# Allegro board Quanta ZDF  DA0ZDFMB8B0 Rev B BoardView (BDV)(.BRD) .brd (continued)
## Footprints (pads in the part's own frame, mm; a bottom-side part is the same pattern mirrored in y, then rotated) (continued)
BGA32-DIALOG-DA7219-02VBA
  round 0.254 smd: A1(-0.51,-2.025) A3(-0.51,-1.485) A5(-0.51,-0.945) A7(-0.51,-0.405) A9(-0.51,0.135) A11(-0.51,0.675) A13(-0.51,1.215) A15(-0.51,1.755) B2(-0.17,-1.755) B4(-0.17,-1.215) B6(-0.17,-0.675) B8(-0.17,-0.135) B10(-0.17,0.405) B12(-0.17,0.945) B14(-0.17,1.485) B16(-0.17,2.025) C1(0.17,-2.025) C3(0.17,-1.485) C5(0.17,-0.945) C7(0.17,-0.405) C9(0.17,0.135) C11(0.17,0.675) C13(0.17,1.215) C15(0.17,1.755) D2(0.51,-1.755) D4(0.51,-1.215) D6(0.51,-0.675) D8(0.51,-0.135) D10(0.51,0.405) D12(0.51,0.945) D14(0.51,1.485) D16(0.51,2.025)
BGA56-TEXAS-SN74AVC16T245
  round 0.356 smd: A1(-2.925,-1.625) A2(-2.925,-0.975) A3(-2.925,-0.325) A4(-2.925,0.325) A5(-2.925,0.975) A6(-2.925,1.625) B1(-2.275,-1.625) B2(-2.275,-0.975) B3(-2.275,-0.325) B4(-2.275,0.325) B5(-2.275,0.975) B6(-2.275,1.625) C1(-1.625,-1.625) C2(-1.625,-0.975) C3(-1.625,-0.325) C4(-1.625,0.325) C5(-1.625,0.975) C6(-1.625,1.625) D1(-0.975,-1.625) D2(-0.975,-0.975) D3(-0.975,-0.325) D4(-0.975,0.325) D5(-0.975,0.975) D6(-0.975,1.625) E1(-0.325,-1.625) E2(-0.325,-0.975) E5(-0.325,0.975) E6(-0.325,1.625) F1(0.325,-1.625) F2(0.325,-0.975) F5(0.325,0.975) F6(0.325,1.625) G1(0.975,-1.625) G2(0.975,-0.975) G3(0.975,-0.325) G4(0.975,0.325) G5(0.975,0.975) G6(0.975,1.625) H1(1.625,-1.625) H2(1.625,-0.975) H3(1.625,-0.325) H4(1.625,0.325) H5(1.625,0.975) H6(1.625,1.625) J1(2.275,-1.625) J2(2.275,-0.975) J3(2.275,-0.325) J4(2.275,0.325) J5(2.275,0.975) J6(2.275,1.625) K1(2.925,-1.625) K2(2.925,-0.975) K3(2.925,-0.325) K4(2.925,0.325) K5(2.925,0.975) K6(2.925,1.625)
BGA64-ANALOGIX-ANX7625
  round 0.254 smd: A1(-1.4,-1.4) A2(-1.4,-1) A3(-1.4,-0.6) A4(-1.4,-0.2) A5(-1.4,0.2) A6(-1.4,0.6) A7(-1.4,1) A8(-1.4,1.4) B1(-1,-1.4) B2(-1,-1) B3(-1,-0.6) B4(-1,-0.2) B5(-1,0.2) B6(-1,0.6) B7(-1,1) B8(-1,1.4) C1(-0.6,-1.4) C2(-0.6,-1) C3(-0.6,-0.6) C4(-0.6,-0.2) C5(-0.6,0.2) C6(-0.6,0.6) C7(-0.6,1) C8(-0.6,1.4) D1(-0.2,-1.4) D2(-0.2,-1) D3(-0.2,-0.6) D4(-0.2,-0.2) D5(-0.2,0.2) D6(-0.2,0.6) D7(-0.2,1) D8(-0.2,1.4) E1(0.2,-1.4) E2(0.2,-1) E3(0.2,-0.6) E4(0.2,-0.2) E5(0.2,0.2) E6(0.2,0.6) E7(0.2,1) E8(0.2,1.4) F1(0.6,-1.4) F2(0.6,-1) F3(0.6,-0.6) F4(0.6,-0.2) F5(0.6,0.2) F6(0.6,0.6) F7(0.6,1) F8(0.6,1.4) G1(1,-1.4) G2(1,-1) G3(1,-0.6) G4(1,-0.2) G5(1,0.2) G6(1,0.6) G7(1,1) G8(1,1.4) H1(1.4,-1.4) H2(1.4,-1) H3(1.4,-0.6) H4(1.4,-0.2) H5(1.4,0.2) H6(1.4,0.6) H7(1.4,1) H8(1.4,1.4)
BGA64-ST-SMT32F098RC-0_5S
  round 0.254 smd: A1(-1.75,-1.75) A2(-1.75,-1.25) A3(-1.75,-0.75) A4(-1.75,-0.25) A5(-1.75,0.25) A6(-1.75,0.75) A7(-1.75,1.25) A8(-1.75,1.75) B1(-1.25,-1.75) B2(-1.25,-1.25) B3(-1.25,-0.75) B4(-1.25,-0.25) B5(-1.25,0.25) B6(-1.25,0.75) B7(-1.25,1.25) B8(-1.25,1.75) C1(-0.75,-1.75) C2(-0.75,-1.25) C3(-0.75,-0.75) C4(-0.75,-0.25) C5(-0.75,0.25) C6(-0.75,0.75) C7(-0.75,1.25) C8(-0.75,1.75) D1(-0.25,-1.75) D2(-0.25,-1.25) D3(-0.25,-0.75) D4(-0.25,-0.25) D5(-0.25,0.25) D6(-0.25,0.75) D7(-0.25,1.25) D8(-0.25,1.75) E1(0.25,-1.75) E2(0.25,-1.25) E3(0.25,-0.75) E4(0.25,-0.25) E5(0.25,0.25) E6(0.25,0.75) E7(0.25,1.25) E8(0.25,1.75) F1(0.75,-1.75) F2(0.75,-1.25) F3(0.75,-0.75) F4(0.75,-0.25) F5(0.75,0.25) F6(0.75,0.75) F7(0.75,1.25) F8(0.75,1.75) G1(1.25,-1.75) G2(1.25,-1.25) G3(1.25,-0.75) G4(1.25,-0.25) G5(1.25,0.25) G6(1.25,0.75) G7(1.25,1.25) G8(1.25,1.75) H1(1.75,-1.75) H2(1.75,-1.25) H3(1.75,-0.75) H4(1.75,-0.25) H5(1.75,0.25) H6(1.75,0.75) H7(1.75,1.25) H8(1.75,1.75)
BGA78-GOOGLE-UR0605B
  round 0.254 smd: A1(-2,-2) A2(-2,-1.5) A3(-2,-1) A4(-2,-0.5) A5(-2,0) A6(-2,0.5) A7(-2,1) A8(-2,1.5) A9(-2,2) B1(-1.5,-2) B2(-1.5,-1.5) B3(-1.5,-1) B4(-1.5,-0.5) B5(-1.5,0) B6(-1.5,0.5) B7(-1.5,1) B8(-1.5,1.5) B9(-1.5,2) C1(-1,-2) C2(-1,-1.5) C3(-1,-1) C4(-1,-0.5) C5(-1,0) C7(-1,1) C8(-1,1.5) C9(-1,2) D1(-0.5,-2) D2(-0.5,-1.5) D4(-0.5,-0.5) D5(-0.5,0) D6(-0.5,0.5) D7(-0.5,1) D8(-0.5,1.5) D9(-0.5,2) E1(0,-2) E2(0,-1.5) E3(0,-1) E4(0,-0.5) E5(0,0) E6(0,0.5) E7(0,1) E8(0,1.5) E9(0,2) F1(0.5,-2) F2(0.5,-1.5) F3(0.5,-1) F4(0.5,-0.5) F5(0.5,0) F6(0.5,0.5) F7(0.5,1) F8(0.5,1.5) F9(0.5,2) G1(1,-2) G2(1,-1.5) G3(1,-1) G5(1,0) G6(1,0.5) G7(1,1) G8(1,1.5) G9(1,2) H1(1.5,-2) H2(1.5,-1.5) H3(1.5,-1) H4(1.5,-0.5) H5(1.5,0) H6(1.5,0.5) H7(1.5,1) H8(1.5,1.5) H9(1.5,2) J1(2,-2) J2(2,-1.5) J3(2,-1) J4(2,-0.5) J5(2,0) J6(2,0.5) J7(2,1) J8(2,1.5) J9(2,2)
BGA153-SANDISK-SDIN7DP4-16G
  round 0.254 smd: A1(-3.25,-3.25) A2(-3.25,-2.75) A3(-3.25,-2.25) A4(-3.25,-1.75) A5(-3.25,-1.25) A6(-3.25,-0.75) A7(-3.25,-0.25) A8(-3.25,0.25) A9(-3.25,0.75) A10(-3.25,1.25) A11(-3.25,1.75) A12(-3.25,2.25) A13(-3.25,2.75) A14(-3.25,3.25) B1(-2.75,-3.25) B2(-2.75,-2.75) B3(-2.75,-2.25) B4(-2.75,-1.75) B5(-2.75,-1.25) B6(-2.75,-0.75) B7(-2.75,-0.25) B8(-2.75,0.25) B9(-2.75,0.75) B10(-2.75,1.25) B11(-2.75,1.75) B12(-2.75,2.25) B13(-2.75,2.75) B14(-2.75,3.25) C1(-2.25,-3.25) C2(-2.25,-2.75) C3(-2.25,-2.25) C4(-2.25,-1.75) C5(-2.25,-1.25) C6(-2.25,-0.75) C7(-2.25,-0.25) C8(-2.25,0.25) C9(-2.25,0.75) C10(-2.25,1.25) C11(-2.25,1.75) C12(-2.25,2.25) C13(-2.25,2.75) C14(-2.25,3.25) D1(-1.75,-3.25) D2(-1.75,-2.75) D3(-1.75,-2.25) D4(-1.75,-1.75) D12(-1.75,2.25) D13(-1.75,2.75) D14(-1.75,3.25) E1(-1.25,-3.25) E2(-1.25,-2.75) E3(-1.25,-2.25) E5(-1.25,-1.25) E6(-1.25,-0.75) E7(-1.25,-0.25) E8(-1.25,0.25) E9(-1.25,0.75) E10(-1.25,1.25) E12(-1.25,2.25) E13(-1.25,2.75) E14(-1.25,3.25) F1(-0.75,-3.25) F2(-0.75,-2.75) F3(-0.75,-2.25) F5(-0.75,-1.25) F10(-0.75,1.25) F12(-0.75,2.25) F13(-0.75,2.75) F14(-0.75,3.25) G1(-0.25,-3.25) G2(-0.25,-2.75) G3(-0.25,-2.25) G5(-0.25,-1.25) G10(-0.25,1.25) G12(-0.25,2.25) G13(-0.25,2.75) G14(-0.25,3.25) H1(0.25,-3.25) H2(0.25,-2.75) H3(0.25,-2.25) H5(0.25,-1.25) H10(0.25,1.25) H12(0.25,2.25) H13(0.25,2.75) H14(0.25,3.25) J1(0.75,-3.25) J2(0.75,-2.75) J3(0.75,-2.25) J5(0.75,-1.25) J10(0.75,1.25) J12(0.75,2.25) J13(0.75,2.75) J14(0.75,3.25) K1(1.25,-3.25) K2(1.25,-2.75) K3(1.25,-2.25) K5(1.25,-1.25) K6(1.25,-0.75) K7(1.25,-0.25) K8(1.25,0.25) K9(1.25,0.75) K10(1.25,1.25) K12(1.25,2.25) K13(1.25,2.75) K14(1.25,3.25) L1(1.75,-3.25) L2(1.75,-2.75) L3(1.75,-2.25) L12(1.75,2.25) L13(1.75,2.75) L14(1.75,3.25) M1(2.25,-3.25) M2(2.25,-2.75) M3(2.25,-2.25) M4(2.25,-1.75) M5(2.25,-1.25) M6(2.25,-0.75) M7(2.25,-0.25) M8(2.25,0.25) M9(2.25,0.75) M10(2.25,1.25) M11(2.25,1.75) M12(2.25,2.25) M13(2.25,2.75) M14(2.25,3.25) N1(2.75,-3.25) N2(2.75,-2.75) N3(2.75,-2.25) N4(2.75,-1.75) N5(2.75,-1.25) N6(2.75,-0.75) N7(2.75,-0.25) N8(2.75,0.25) N9(2.75,0.75) N10(2.75,1.25) N11(2.75,1.75) N12(2.75,2.25) N13(2.75,2.75) N14(2.75,3.25) P1(3.25,-3.25) P2(3.25,-2.75) P3(3.25,-2.25) P4(3.25,-1.75) P5(3.25,-1.25) P6(3.25,-0.75) P7(3.25,-0.25) P8(3.25,0.25) P9(3.25,0.75) P10(3.25,1.25) P11(3.25,1.75) P12(3.25,2.25) P13(3.25,2.75) P14(3.25,3.25)
BGA194-MEDIATEK-MT6358-0_5S
  round 0.254 smd: A1(-2.8,-3) A2(-2.8,-2.6) A3(-2.8,-2.2) A4(-2.8,-1.8) A5(-2.8,-1.4) A6(-2.8,-1) A7(-2.8,-0.6) A8(-2.8,-0.2) A9(-2.8,0.2) A10(-2.8,0.6) A11(-2.8,1) A12(-2.8,1.4) A13(-2.8,1.8) A14(-2.8,2.2) A15(-2.8,2.6) A16(-2.8,3) B1(-2.4,-3) B2(-2.4,-2.6) B3(-2.4,-2.2) B4(-2.4,-1.8) B6(-2.4,-1) B7(-2.4,-0.6) B8(-2.4,-0.2) B9(-2.4,0.2) B10(-2.4,0.6) B11(-2.4,1) B12(-2.4,1.4) B13(-2.4,1.8) B14(-2.4,2.2) B15(-2.4,2.6) B16(-2.4,3) C1(-2,-3) C15(-2,2.6) C16(-2,3) D2(-1.6,-2.6) D3(-1.6,-2.2) D4(-1.6,-1.8) D5(-1.6,-1.4) D6(-1.6,-1) D7(-1.6,-0.6) D8(-1.6,-0.2) D9(-1.6,0.2) D10(-1.6,0.6) D11(-1.6,1) D12(-1.6,1.4) D13(-1.6,1.8) D14(-1.6,2.2) D15(-1.6,2.6) D16(-1.6,3) E1(-1.2,-3) E2(-1.2,-2.6) E3(-1.2,-2.2) E4(-1.2,-1.8) E5(-1.2,-1.4) E6(-1.2,-1) E7(-1.2,-0.6) E8(-1.2,-0.2) E9(-1.2,0.2) E12(-1.2,1.4) E14(-1.2,2.2) F1(-0.8,-3) F2(-0.8,-2.6) F3(-0.8,-2.2) F5(-0.8,-1.4) F6(-0.8,-1) F7(-0.8,-0.6) F8(-0.8,-0.2) F9(-0.8,0.2) F10(-0.8,0.6) F11(-0.8,1) F12(-0.8,1.4) F13(-0.8,1.8) F14(-0.8,2.2) F15(-0.8,2.6) F16(-0.8,3) G2(-0.4,-2.6) G4(-0.4,-1.8) G5(-0.4,-1.4) G6(-0.4,-1) G7(-0.4,-0.6) G8(-0.4,-0.2) G9(-0.4,0.2) G10(-0.4,0.6) G11(-0.4,1) G12(-0.4,1.4) G13(-0.4,1.8) G15(-0.4,2.6) G16(-0.4,3) H1(0,-3) H2(0,-2.6) H4(0,-1.8) H5(0,-1.4) H6(0,-1) H7(0,-0.6) H8(0,-0.2) H9(0,0.2) H10(0,0.6) H11(0,1) H13(0,1.8) H15(0,2.6) J3(0.4,-2.2) J4(0.4,-1.8) J5(0.4,-1.4) J6(0.4,-1) J7(0.4,-0.6) J8(0.4,-0.2) J9(0.4,0.2) J10(0.4,0.6) J11(0.4,1) J13(0.4,1.8) J15(0.4,2.6) J16(0.4,3) K1(0.8,-3) K3(0.8,-2.2) K4(0.8,-1.8) K5(0.8,-1.4) K6(0.8,-1) K10(0.8,0.6) K12(0.8,1.4) K13(0.8,1.8) K15(0.8,2.6) K16(0.8,3) L1(1.2,-3) L3(1.2,-2.2) L4(1.2,-1.8) L5(1.2,-1.4) L6(1.2,-1) L7(1.2,-0.6) L8(1.2,-0.2) L9(1.2,0.2) L10(1.2,0.6) L11(1.2,1) L12(1.2,1.4) L13(1.2,1.8) L14(1.2,2.2) L15(1.2,2.6) L16(1.2,3) M2(1.6,-2.6) M3(1.6,-2.2) M4(1.6,-1.8) M5(1.6,-1.4) M6(1.6,-1) M7(1.6,-0.6) M8(1.6,-0.2) M9(1.6,0.2) M10(1.6,0.6) M11(1.6,1) M12(1.6,1.4) M13(1.6,1.8) M14(1.6,2.2) M15(1.6,2.6) N1(2,-3) N2(2,-2.6) N4(2,-1.8) N6(2,-1) N7(2,-0.6) N8(2,-0.2) N9(2,0.2) N10(2,0.6) N11(2,1) N12(2,1.4) N13(2,1.8) N14(2,2.2) N15(2,2.6) N16(2,3) P1(2.4,-3) P2(2.4,-2.6) P3(2.4,-2.2) P4(2.4,-1.8) P5(2.4,-1.4) P6(2.4,-1) P7(2.4,-0.6) P8(2.4,-0.2) P9(2.4,0.2) P10(2.4,0.6) P11(2.4,1) P12(2.4,1.4) P13(2.4,1.8) P14(2.4,2.2) P15(2.4,2.6) P16(2.4,3) R1(2.8,-3) R2(2.8,-2.6) R3(2.8,-2.2) R5(2.8,-1.4) R6(2.8,-1) R7(2.8,-0.6) R9(2.8,0.2) R10(2.8,0.6) R11(2.8,1) R13(2.8,1.8) R14(2.8,2.2) R15(2.8,2.6) R16(2.8,3)
BGA200-HYNIX-H9HCNNN8RUMLHR
  round 0.254 smd: A1(-6.825,-4.4) A2(-6.825,-3.6) A3(-6.825,-2.8) A4(-6.825,-2) A5(-6.825,-1.2) A8(-6.825,1.2) A9(-6.825,2) A10(-6.825,2.8) A11(-6.825,3.6) A12(-6.825,4.4) AA1(6.175,-4.4) AA2(6.175,-3.6) AA3(6.175,-2.8) AA4(6.175,-2) AA5(6.175,-1.2) AA8(6.175,1.2) AA9(6.175,2) AA10(6.175,2.8) AA11(6.175,3.6) AA12(6.175,4.4) AB1(6.825,-4.4) AB2(6.825,-3.6) AB3(6.825,-2.8) AB4(6.825,-2) AB5(6.825,-1.2) AB8(6.825,1.2) AB9(6.825,2) AB10(6.825,2.8) AB11(6.825,3.6) AB12(6.825,4.4) B1(-6.175,-4.4) B2(-6.175,-3.6) B3(-6.175,-2.8) B4(-6.175,-2) B5(-6.175,-1.2) B8(-6.175,1.2) B9(-6.175,2) B10(-6.175,2.8) B11(-6.175,3.6) B12(-6.175,4.4) C1(-5.525,-4.4) C2(-5.525,-3.6) C3(-5.525,-2.8) C4(-5.525,-2) C5(-5.525,-1.2) C8(-5.525,1.2) C9(-5.525,2) C10(-5.525,2.8) C11(-5.525,3.6) C12(-5.525,4.4) D1(-4.875,-4.4) D2(-4.875,-3.6) D3(-4.875,-2.8) D4(-4.875,-2) D5(-4.875,-1.2) D8(-4.875,1.2) D9(-4.875,2) D10(-4.875,2.8) D11(-4.875,3.6) D12(-4.875,4.4) E1(-4.225,-4.4) E2(-4.225,-3.6) E3(-4.225,-2.8) E4(-4.225,-2) E5(-4.225,-1.2) E8(-4.225,1.2) E9(-4.225,2) E10(-4.225,2.8) E11(-4.225,3.6) E12(-4.225,4.4) F1(-3.575,-4.4) F2(-3.575,-3.6) F3(-3.575,-2.8) F4(-3.575,-2) F5(-3.575,-1.2) F8(-3.575,1.2) F9(-3.575,2) F10(-3.575,2.8) F11(-3.575,3.6) F12(-3.575,4.4) G1(-2.925,-4.4) G2(-2.925,-3.6) G3(-2.925,-2.8) G4(-2.925,-2) G5(-2.925,-1.2) G8(-2.925,1.2) G9(-2.925,2) G10(-2.925,2.8) G11(-2.925,3.6) G12(-2.925,4.4) H1(-2.275,-4.4) H2(-2.275,-3.6) H3(-2.275,-2.8) H4(-2.275,-2) H5(-2.275,-1.2) H8(-2.275,1.2) H9(-2.275,2) H10(-2.275,2.8) H11(-2.275,3.6) H12(-2.275,4.4) J1(-1.625,-4.4) J2(-1.625,-3.6) J3(-1.625,-2.8) J4(-1.625,-2) J5(-1.625,-1.2) J8(-1.625,1.2) J9(-1.625,2) J10(-1.625,2.8) J11(-1.625,3.6) J12(-1.625,4.4) K1(-0.975,-4.4) K2(-0.975,-3.6) K3(-0.975,-2.8) K4(-0.975,-2) K5(-0.975,-1.2) K8(-0.975,1.2) K9(-0.975,2) K10(-0.975,2.8) K11(-0.975,3.6) K12(-0.975,4.4) N1(0.975,-4.4) N2(0.975,-3.6) N3(0.975,-2.8) N4(0.975,-2) N5(0.975,-1.2) N8(0.975,1.2) N9(0.975,2) N10(0.975,2.8) N11(0.975,3.6) N12(0.975,4.4) P1(1.625,-4.4) P2(1.625,-3.6) P3(1.625,-2.8) P4(1.625,-2) P5(1.625,-1.2) P8(1.625,1.2) P9(1.625,2) P10(1.625,2.8) P11(1.625,3.6) P12(1.625,4.4) R1(2.275,-4.4) R2(2.275,-3.6) R3(2.275,-2.8) R4(2.275,-2) R5(2.275,-1.2) R8(2.275,1.2) R9(2.275,2) R10(2.275,2.8) R11(2.275,3.6) R12(2.275,4.4) T1(2.925,-4.4) T2(2.925,-3.6) T3(2.925,-2.8) T4(2.925,-2) T5(2.925,-1.2) T8(2.925,1.2) T9(2.925,2) T10(2.925,2.8) T11(2.925,3.6) T12(2.925,4.4) U1(3.575,-4.4) U2(3.575,-3.6) U3(3.575,-2.8) U4(3.575,-2) U5(3.575,-1.2) U8(3.575,1.2) U9(3.575,2) U10(3.575,2.8) U11(3.575,3.6) U12(3.575,4.4) V1(4.225,-4.4) V2(4.225,-3.6) V3(4.225,-2.8) V4(4.225,-2) V5(4.225,-1.2) V8(4.225,1.2) V9(4.225,2) V10(4.225,2.8) V11(4.225,3.6) V12(4.225,4.4) W1(4.875,-4.4) W2(4.875,-3.6) W3(4.875,-2.8) W4(4.875,-2) W5(4.875,-1.2) W8(4.875,1.2) W9(4.875,2) W10(4.875,2.8) W11(4.875,3.6) W12(4.875,4.4) Y1(5.525,-4.4) Y2(5.525,-3.6) Y3(5.525,-2.8) Y4(5.525,-2) Y5(5.525,-1.2) Y8(5.525,1.2) Y9(5.525,2) Y10(5.525,2.8) Y11(5.525,3.6) Y12(5.525,4.4)
BGA599-MEDIA-MT8183-0_5S
  round 0.254 smd: A1(-5.6,-5.2) A2(-5.6,-4.8) A3(-5.6,-4.4) A5(-5.6,-3.6) A7(-5.6,-2.8) A9(-5.6,-2) A11(-5.6,-1.2) A13(-5.6,-0.4) A15(-5.6,0.4) A17(-5.6,1.2) A19(-5.6,2) A21(-5.6,2.8) A22(-5.6,3.2) A24(-5.6,4) A26(-5.6,4.8) A27(-5.6,5.2) AA1(2.4,-5.2) AA2(2.4,-4.8) AA3(2.4,-4.4) AA4(2.4,-4) AA5(2.4,-3.6) AA6(2.4,-3.2) AA7(2.4,-2.8) AA10(2.4,-1.6) AA12(2.4,-0.8) AA13(2.4,-0.4) AA15(2.4,0.4) AA17(2.4,1.2) AA19(2.4,2) AA21(2.4,2.8) AA22(2.4,3.2) AA23(2.4,3.6) AA24(2.4,4) AA25(2.4,4.4) AA26(2.4,4.8) AA27(2.4,5.2) AB1(2.8,-5.2) AB2(2.8,-4.8) AB4(2.8,-4) AB5(2.8,-3.6) AB6(2.8,-3.2) AB7(2.8,-2.8) AB8(2.8,-2.4) AB9(2.8,-2) AB13(2.8,-0.4) AB14(2.8,0) AB16(2.8,0.8) AB18(2.8,1.6) AB20(2.8,2.4) AB21(2.8,2.8) AB22(2.8,3.2) AB23(2.8,3.6) AB24(2.8,4) AB25(2.8,4.4) AB26(2.8,4.8) AB27(2.8,5.2) AC2(3.2,-4.8) AC3(3.2,-4.4) AC4(3.2,-4) AC5(3.2,-3.6) AC6(3.2,-3.2) AC7(3.2,-2.8) AC9(3.2,-2) AC10(3.2,-1.6) AC11(3.2,-1.2) AC12(3.2,-0.8) AC13(3.2,-0.4) AC14(3.2,0) AC15(3.2,0.4) AC17(3.2,1.2) AC19(3.2,2) AC22(3.2,3.2) AC23(3.2,3.6) AC24(3.2,4) AC25(3.2,4.4) AC26(3.2,4.8) AD1(3.6,-5.2) AD2(3.6,-4.8) AD4(3.6,-4) AD5(3.6,-3.6) AD6(3.6,-3.2) AD7(3.6,-2.8) AD8(3.6,-2.4) AD9(3.6,-2) AD10(3.6,-1.6) AD16(3.6,0.8) AD19(3.6,2) AD20(3.6,2.4) AD21(3.6,2.8) AD22(3.6,3.2) AD23(3.6,3.6) AD24(3.6,4) AD25(3.6,4.4) AD26(3.6,4.8) AD27(3.6,5.2) AE1(4,-5.2) AE2(4,-4.8) AE3(4,-4.4) AE4(4,-4) AE5(4,-3.6) AE6(4,-3.2) AE7(4,-2.8) AE10(4,-1.6) AE11(4,-1.2) AE12(4,-0.8) AE13(4,-0.4) AE14(4,0) AE15(4,0.4) AE16(4,0.8) AE17(4,1.2) AE18(4,1.6) AE19(4,2) AE20(4,2.4) AE21(4,2.8) AE22(4,3.2) AE23(4,3.6) AE24(4,4) AE25(4,4.4) AE26(4,4.8) AE27(4,5.2) AF2(4.4,-4.8) AF3(4.4,-4.4) AF4(4.4,-4) AF5(4.4,-3.6) AF6(4.4,-3.2) AF7(4.4,-2.8) AF8(4.4,-2.4) AF9(4.4,-2) AF11(4.4,-1.2) AF12(4.4,-0.8) AF13(4.4,-0.4) AF14(4.4,0) AF15(4.4,0.4) AF16(4.4,0.8) AF17(4.4,1.2) AF18(4.4,1.6) AF19(4.4,2) AF20(4.4,2.4) AF21(4.4,2.8) AF22(4.4,3.2) AF23(4.4,3.6) AF24(4.4,4) AF25(4.4,4.4) AF26(4.4,4.8) AG1(4.8,-5.2) AG2(4.8,-4.8) AG3(4.8,-4.4) AG4(4.8,-4) AG5(4.8,-3.6) AG6(4.8,-3.2) AG7(4.8,-2.8) AG8(4.8,-2.4) AG9(4.8,-2) AG11(4.8,-1.2) AG12(4.8,-0.8) AG13(4.8,-0.4) AG14(4.8,0) AG15(4.8,0.4) AG16(4.8,0.8) AG17(4.8,1.2) AG18(4.8,1.6) AG19(4.8,2) AG20(4.8,2.4) AG21(4.8,2.8) AG22(4.8,3.2) AG23(4.8,3.6) AG24(4.8,4) AG25(4.8,4.4) AG26(4.8,4.8) AG27(4.8,5.2) AH1(5.2,-5.2) AH2(5.2,-4.8) AH3(5.2,-4.4) AH4(5.2,-4) AH5(5.2,-3.6) AH6(5.2,-3.2) AH7(5.2,-2.8) AH8(5.2,-2.4) AH9(5.2,-2) AH10(5.2,-1.6) AH11(5.2,-1.2) AH12(5.2,-0.8) AH13(5.2,-0.4) AH14(5.2,0) AH15(5.2,0.4) AH16(5.2,0.8) AH17(5.2,1.2) AH18(5.2,1.6) AH19(5.2,2) AH20(5.2,2.4) AH21(5.2,2.8) AH22(5.2,3.2) AH23(5.2,3.6) AH24(5.2,4) AH25(5.2,4.4) AH26(5.2,4.8) AH27(5.2,5.2) AJ1(5.6,-5.2) AJ2(5.6,-4.8) AJ4(5.6,-4) AJ5(5.6,-3.6) AJ7(5.6,-2.8) AJ8(5.6,-2.4) AJ9(5.6,-2) AJ10(5.6,-1.6) AJ12(5.6,-0.8) AJ13(5.6,-0.4) AJ15(5.6,0.4) AJ16(5.6,0.8) AJ18(5.6,1.6) AJ21(5.6,2.8) AJ22(5.6,3.2) AJ24(5.6,4) AJ25(5.6,4.4) AJ26(5.6,4.8) AJ27(5.6,5.2) B1(-5.2,-5.2) B2(-5.2,-4.8) B3(-5.2,-4.4) B4(-5.2,-4) B5(-5.2,-3.6) B6(-5.2,-3.2) B7(-5.2,-2.8) B9(-5.2,-2) B10(-5.2,-1.6) B11(-5.2,-1.2) B13(-5.2,-0.4) B14(-5.2,0) B15(-5.2,0.4) B17(-5.2,1.2) B18(-5.2,1.6) B19(-5.2,2) B21(-5.2,2.8) B22(-5.2,3.2) B23(-5.2,3.6) B24(-5.2,4) B25(-5.2,4.4) B26(-5.2,4.8) B27(-5.2,5.2) C1(-4.8,-5.2) C2(-4.8,-4.8) C3(-4.8,-4.4) C4(-4.8,-4) C5(-4.8,-3.6) C6(-4.8,-3.2) C7(-4.8,-2.8) C8(-4.8,-2.4) C9(-4.8,-2) C10(-4.8,-1.6) C11(-4.8,-1.2) C12(-4.8,-0.8) C13(-4.8,-0.4) C14(-4.8,0) C15(-4.8,0.4) C16(-4.8,0.8) C17(-4.8,1.2) C18(-4.8,1.6) C19(-4.8,2) C20(-4.8,2.4) C21(-4.8,2.8) C22(-4.8,3.2) C23(-4.8,3.6) C24(-4.8,4) C25(-4.8,4.4) C26(-4.8,4.8) C27(-4.8,5.2) D1(-4.4,-5.2) D2(-4.4,-4.8) D3(-4.4,-4.4) D4(-4.4,-4) D5(-4.4,-3.6) D6(-4.4,-3.2) D7(-4.4,-2.8) D8(-4.4,-2.4) D9(-4.4,-2) D10(-4.4,-1.6) D11(-4.4,-1.2) D12(-4.4,-0.8) D14(-4.4,0) D15(-4.4,0.4) D16(-4.4,0.8) D17(-4.4,1.2) D18(-4.4,1.6) D19(-4.4,2) D20(-4.4,2.4) D21(-4.4,2.8) D22(-4.4,3.2) D23(-4.4,3.6) D24(-4.4,4) D25(-4.4,4.4) D26(-4.4,4.8) E2(-4,-4.8) E3(-4,-4.4) E4(-4,-4) E5(-4,-3.6) E6(-4,-3.2) E7(-4,-2.8) E8(-4,-2.4) E9(-4,-2) E10(-4,-1.6) E11(-4,-1.2) E12(-4,-0.8) E13(-4,-0.4) E14(-4,0) E15(-4,0.4) E16(-4,0.8) E17(-4,1.2) E18(-4,1.6) E19(-4,2) E20(-4,2.4) E21(-4,2.8) E22(-4,3.2) E24(-4,4) E25(-4,4.4) E26(-4,4.8) E27(-4,5.2) F1(-3.6,-5.2) F2(-3.6,-4.8) F3(-3.6,-4.4) F4(-3.6,-4) F5(-3.6,-3.6) F9(-3.6,-2) F10(-3.6,-1.6) F11(-3.6,-1.2) F12(-3.6,-0.8) F13(-3.6,-0.4) F16(-3.6,0.8) F17(-3.6,1.2) F18(-3.6,1.6) F19(-3.6,2) F20(-3.6,2.4) F21(-3.6,2.8) F23(-3.6,3.6) F24(-3.6,4) F25(-3.6,4.4) F26(-3.6,4.8) F27(-3.6,5.2) G1(-3.2,-5.2) G2(-3.2,-4.8) G3(-3.2,-4.4) G4(-3.2,-4) G5(-3.2,-3.6) G6(-3.2,-3.2) G9(-3.2,-2) G14(-3.2,0) G15(-3.2,0.4) G18(-3.2,1.6) G21(-3.2,2.8) G23(-3.2,3.6) G24(-3.2,4) G25(-3.2,4.4) G26(-3.2,4.8) H2(-2.8,-4.8) H3(-2.8,-4.4) H4(-2.8,-4) H5(-2.8,-3.6) H6(-2.8,-3.2) H8(-2.8,-2.4) H10(-2.8,-1.6) H11(-2.8,-1.2) H12(-2.8,-0.8) H13(-2.8,-0.4) H16(-2.8,0.8) H17(-2.8,1.2) H19(-2.8,2) H21(-2.8,2.8) H22(-2.8,3.2) H23(-2.8,3.6) H24(-2.8,4) H25(-2.8,4.4) H26(-2.8,4.8) H27(-2.8,5.2) J1(-2.4,-5.2) J2(-2.4,-4.8) J3(-2.4,-4.4) J4(-2.4,-4) J5(-2.4,-3.6) J6(-2.4,-3.2) J7(-2.4,-2.8) J8(-2.4,-2.4) J10(-2.4,-1.6) J11(-2.4,-1.2) J12(-2.4,-0.8) J13(-2.4,-0.4) J14(-2.4,0) J15(-2.4,0.4) J16(-2.4,0.8) J17(-2.4,1.2) J19(-2.4,2) J20(-2.4,2.4) J22(-2.4,3.2) J23(-2.4,3.6) J24(-2.4,4) J25(-2.4,4.4) J26(-2.4,4.8) J27(-2.4,5.2) K3(-2,-4.4) K4(-2,-4) K5(-2,-3.6) K6(-2,-3.2) K10(-2,-1.6) K12(-2,-0.8) K14(-2,0) K16(-2,0.8) K18(-2,1.6) K22(-2,3.2) K23(-2,3.6) K24(-2,4) K25(-2,4.4) K26(-2,4.8) K27(-2,5.2) L1(-1.6,-5.2) L2(-1.6,-4.8) L3(-1.6,-4.4) L4(-1.6,-4) L5(-1.6,-3.6) L9(-1.6,-2) L11(-1.6,-1.2) L13(-1.6,-0.4) L15(-1.6,0.4) L17(-1.6,1.2) L19(-1.6,2) L22(-1.6,3.2) L23(-1.6,3.6) L24(-1.6,4) L25(-1.6,4.4) L26(-1.6,4.8) M1(-1.2,-5.2) M2(-1.2,-4.8) M3(-1.2,-4.4) M4(-1.2,-4) M5(-1.2,-3.6) M10(-1.2,-1.6) M12(-1.2,-0.8) M14(-1.2,0) M16(-1.2,0.8) M18(-1.2,1.6) M20(-1.2,2.4) M22(-1.2,3.2) M23(-1.2,3.6) M24(-1.2,4) M25(-1.2,4.4) M26(-1.2,4.8) M27(-1.2,5.2) N1(-0.8,-5.2) N2(-0.8,-4.8) N3(-0.8,-4.4) N4(-0.8,-4) N5(-0.8,-3.6) N9(-0.8,-2) N11(-0.8,-1.2) N13(-0.8,-0.4) N15(-0.8,0.4) N17(-0.8,1.2) N19(-0.8,2) N21(-0.8,2.8) N22(-0.8,3.2) N23(-0.8,3.6) N24(-0.8,4) N25(-0.8,4.4) N26(-0.8,4.8) N27(-0.8,5.2) P1(-0.4,-5.2) P2(-0.4,-4.8) P3(-0.4,-4.4) P4(-0.4,-4) P5(-0.4,-3.6) P7(-0.4,-2.8) P10(-0.4,-1.6) P12(-0.4,-0.8) P14(-0.4,0) P16(-0.4,0.8) P18(-0.4,1.6) P20(-0.4,2.4) P21(-0.4,2.8) P22(-0.4,3.2) P23(-0.4,3.6) P24(-0.4,4) P25(-0.4,4.4) P26(-0.4,4.8) R1(0,-5.2) R2(0,-4.8) R3(0,-4.4) R4(0,-4) R5(0,-3.6) R7(0,-2.8) R8(0,-2.4) R9(0,-2) R11(0,-1.2) R13(0,-0.4) R15(0,0.4) R17(0,1.2) R19(0,2) R22(0,3.2) R23(0,3.6) R24(0,4) R25(0,4.4) R26(0,4.8) R27(0,5.2) T1(0.4,-5.2) T2(0.4,-4.8) T3(0.4,-4.4) T4(0.4,-4) T5(0.4,-3.6) T7(0.4,-2.8) T8(0.4,-2.4) T10(0.4,-1.6) T11(0.4,-1.2) T12(0.4,-0.8) T14(0.4,0) T16(0.4,0.8) T18(0.4,1.6) T20(0.4,2.4) T21(0.4,2.8) T22(0.4,3.2) T23(0.4,3.6) T24(0.4,4) T25(0.4,4.4) T26(0.4,4.8) T27(0.4,5.2) U1(0.8,-5.2) U2(0.8,-4.8) U3(0.8,-4.4) U4(0.8,-4) U5(0.8,-3.6) U7(0.8,-2.8) U8(0.8,-2.4) U9(0.8,-2) U10(0.8,-1.6) U13(0.8,-0.4) U15(0.8,0.4) U17(0.8,1.2) U19(0.8,2) U21(0.8,2.8) U23(0.8,3.6) U24(0.8,4) U25(0.8,4.4) U26(0.8,4.8) V1(1.2,-5.2) V2(1.2,-4.8) V3(1.2,-4.4) V4(1.2,-4) V5(1.2,-3.6) V8(1.2,-2.4) V9(1.2,-2) V10(1.2,-1.6) V12(1.2,-0.8) V14(1.2,0) V16(1.2,0.8) V18(1.2,1.6) V20(1.2,2.4) V21(1.2,2.8) V22(1.2,3.2) V23(1.2,3.6) V24(1.2,4) V25(1.2,4.4) V26(1.2,4.8) V27(1.2,5.2) W1(1.6,-5.2) W2(1.6,-4.8) W3(1.6,-4.4) W4(1.6,-4) W5(1.6,-3.6) W6(1.6,-3.2) W7(1.6,-2.8) W9(1.6,-2) W11(1.6,-1.2) W12(1.6,-0.8) W13(1.6,-0.4) W15(1.6,0.4) W17(1.6,1.2) W19(1.6,2) W21(1.6,2.8) W22(1.6,3.2) W23(1.6,3.6) W24(1.6,4) W25(1.6,4.4) W26(1.6,4.8) W27(1.6,5.2) Y2(2,-4.8) Y4(2,-4) Y5(2,-3.6) Y6(2,-3.2) Y7(2,-2.8) Y8(2,-2.4) Y9(2,-2) Y10(2,-1.6) Y12(2,-0.8) Y13(2,-0.4) Y14(2,0) Y15(2,0.4) Y16(2,0.8) Y18(2,1.6) Y20(2,2.4) Y22(2,3.2) Y23(2,3.6) Y24(2,4) Y25(2,4.4) Y26(2,4.8)
C0201
  rect 0.203x0.381 smd: 1(-0.225,0) 2(0.225,0)
C0402
  custom 0.12x0.12 smd: 1(0.39,0) 2(-0.39,0)
C0402_2
  custom 0.12x0.12 smd: 1(0.39,0) 2(-0.39,0)
C0603
  rect 0.686x0.813 smd: 1(0.6,0) 2(-0.6,0)
C0805
  rect 0.864x1.372 smd: 1(0.88,0) 2(-0.88,0)
CHOKE-DLP11RN450UL2L-4P
  rect 0.508x0.305 smd: 1(-0.525,-0.275) 2(0.525,-0.275) 3(0.525,0.275) 4(-0.525,0.275)
CHOKE-DLP11SN900HL2L-4P-1
  rect 0.711x0.305 smd: 1(-0.625,0.275) 2(0.625,0.275) 3(0.625,-0.275) 4(-0.625,-0.275)
CLIP-39X39-89X20-3P
  rect 2.261x0.508 smd: 1(-2.125,0) 3(2.125,0)
  rect 0.991x0.991 smd: 2(0,0)
D-1_6X1
  rect 0.635x0.991 smd: 1(-0.55,0) 2(0.55,0)
D-1_7X0_9
  rect 0.61x0.787 smd: 1(-0.85,0) 2(0.85,0)
D-1X0_6-0_6H
  rect 0.559x0.61 smd: 1(-0.425,0) 2(0.425,0)
D-1X0_6-D24V0L1B2LPS
  rect 0.457x0.61 smd: 1(-0.375,0) 2(0.375,0)
DFN6-1_1X1-35-SMT
  rect 0.406x0.152 smd: 1(0.501,-0.35) 2(0.501,0) 3(0.501,0.35) 4(-0.501,0.35) 5(-0.501,0) 6(-0.501,-0.35)
DFN6-2X2-65-7P
  rect 0.94x0.356 smd: 1(1.125,-0.65) 2(1.125,0) 3(1.125,0.65) 4(-1.125,0.65) 5(-1.125,0) 6(-1.125,-0.65)
  rect 0.686x1.219 smd: 7(0,0)
DFN14-3X2-4-11P-RT9740A
  rect 0.61x0.787 smd: 1(-1,-1) 6(1,-1) 8(1,1) 13(-1,1)
  rect 0.203x0.787 smd: 3(-0.4,-1) 4(0,-1) 5(0.4,-1) 10(0.4,1) 11(0,1) 12(-0.4,1)
  rect 2.388x0.787 smd: 15(0,0)
DFN1006-3-1X0_6-3P
  rect 0.406x0.254 smd: 1(0.35,-0.225) 2(0.35,0.225)
  rect 0.406x0.711 smd: 3(-0.35,0)
ESD3-0_985X0_585
  custom 0.062x0.062 smd: 1(0.35,-0.225) 2(0.35,0.225)
  custom 0.1x0.1 smd: 3(-0.35,0)
ESD10-2_5X1-5-9P-AZ1143
  rect 0.254x0.686 smd: 1(-1,-0.437) 2(-0.5,-0.437) 4(0.5,-0.437) 5(1,-0.437) 6(1,0.437) 7(0.5,0.437) 9(-0.5,0.437) 10(-1,0.437)
  rect 0.381x1.549 smd: 3(0,0)
F4_55X3_24-5_23-1_8H
  rect 1.778x3.505 smd: 1(-2.615,0) 2(2.615,0)
FPC-50506-00601-V01-6P-L
  rect 0.305x0.889 smd: 1(-1.25,3.05) 2(-0.75,3.05) 3(-0.25,3.05) 4(0.25,3.05) 5(0.75,3.05) 6(1.25,3.05)
  rect 0.991x2.007 smd: 7(-3.35,0) 8(3.35,0)
FPC-51643-0300N-V01-30P-L
  rect 0.305x1.295 smd: 1(-11.6,5.65) 2(-10.8,5.65) 3(-10,5.65) 4(-9.2,5.65) 5(-8.4,5.65) 6(-7.6,5.65) 7(-6.8,5.65) 8(-6,5.65) 9(-5.2,5.65) 10(-4.4,5.65) 11(-3.6,5.65) 12(-2.8,5.65) 13(-2,5.65) 14(-1.2,5.65) 15(-0.4,5.65) 16(0.4,5.65) 17(1.2,5.65) 18(2,5.65) 19(2.8,5.65) 20(3.6,5.65) 21(4.4,5.65) 22(5.2,5.65) 23(6,5.65) 24(6.8,5.65) 25(7.6,5.65) 26(8.4,5.65) 27(9.2,5.65) 28(10,5.65) 29(10.8,5.65) 30(11.6,5.65)
  rect 1.803x2.21 smd: 31(-13.95,0) 32(13.95,0)
H-C276D110P2
  round 7.01 hole 2.794: 1(0,0)
H-C276D118P2
  round 7.01 hole 2.997: 1(0,0)
H-C315D177P2
  round 8.001 hole 4.496: 1(0,0)
H-O118X157D118X157N
  oval 2.997x3.988 hole 2.997x3.988 unplated: (0,0)
H-TC276IBC236D110P2
  round 7.01 hole 2.794: 1(0,0)
H-TC315IBC236D118P2
  round 8.001 hole 2.997: 1(0,0)
H-ZDE-1P2
  round 8.001 hole 2.997: 1(0,0)
L2_5X2-1-HTEN25201T
  rect 0.991x2.108 smd: 1(-0.8,0) 2(0.8,0)
L2_5X2-1_2
  rect 0.787x2.007 smd: 1(-1,0) 2(1,0)
L2X1_6-1H-2P
  rect 0.787x1.702 smd: 1(-0.65,0) 2(0.65,0)
L3_1X3_1
  rect 1.6x1.194 smd: 1(-1.3,0) 2(1.3,0)
L5_1X5_2-1_6H
  rect 1.905x2.489 smd: 1(-2.047,0) 2(2.047,0)
L10_1X10-2H-SMT
  rect 2.21x3.2 smd: 1(-4.25,0) 2(4.25,0)
LED-12-23C-R6GHY2C-A01-2C-4P
  rect 0.61x0.889 smd: 1(-1.4,0) 4(1.4,0)
  rect 0.61x0.559 smd: 2(-0.45,-0.325) 3(0.45,-0.325)
LGA14-3X2_5-5
  rect 0.254x0.686 smd: 1(-0.75,-1.262) 2(-0.25,-1.262) 3(0.25,-1.262) 4(0.75,-1.262) 8(0.75,1.262) 9(0.25,1.262) 10(-0.25,1.262) 11(-0.75,1.262)
  rect 0.686x0.254 smd: 5(1.012,-0.5) 6(1.012,0) 7(1.012,0.5) 12(-1.012,0.5) 13(-1.012,0) 14(-1.012,-0.5)
MLP8-3X2-5-9P
  rect 0.305x0.61 smd: 1(-0.75,-1.3) 2(-0.25,-1.3) 3(0.25,-1.3) 4(0.75,-1.3) 5(0.75,1.3) 6(0.25,1.3) 7(-0.25,1.3) 8(-0.75,1.3)
  rect 1.194x1.194 smd: 9(0,0)
MODULE-16X12-108P-1_63H
  rect 0.305x0.813 smd: 1(-6.75,-5.75) 2(-6.25,-5.75) 3(-5.75,-5.75) 4(-5.25,-5.75) 5(-4.75,-5.75) 6(-4.25,-5.75) 7(-3.75,-5.75) 8(-3.25,-5.75) 9(-2.75,-5.75) 10(-2.25,-5.75) 11(-1.75,-5.75) 12(-1.25,-5.75) 13(-0.75,-5.75) 14(-0.25,-5.75) 15(0.25,-5.75) 16(0.75,-5.75) 17(1.25,-5.75) 18(1.75,-5.75) 19(2.25,-5.75) 20(2.75,-5.75) 21(3.25,-5.75) 22(3.75,-5.75) 23(4.25,-5.75) 24(4.75,-5.75) 25(5.25,-5.75) 26(5.75,-5.75) 27(6.25,-5.75) 28(6.75,-5.75) 49(6.75,5.75) 50(6.25,5.75) 51(5.75,5.75) 52(5.25,5.75) 53(4.75,5.75) 54(4.25,5.75) 55(3.75,5.75) 56(3.25,5.75) 57(2.75,5.75) 58(2.25,5.75) 59(1.75,5.75) 60(1.25,5.75) 61(0.75,5.75) 62(0.25,5.75) 63(-0.25,5.75) 64(-0.75,5.75) 65(-1.25,5.75) 66(-1.75,5.75) 67(-2.25,5.75) 68(-2.75,5.75) 69(-3.25,5.75) 70(-3.75,5.75) 71(-4.25,5.75) 72(-4.75,5.75) 73(-5.25,5.75) 74(-5.75,5.75) 75(-6.25,5.75) 76(-6.75,5.75)
  rect 0.813x0.305 smd: 29(7.75,-4.75) 30(7.75,-4.25) 31(7.75,-3.75) 32(7.75,-3.25) 33(7.75,-2.75) 34(7.75,-2.25) 35(7.75,-1.75) 36(7.75,-1.25) 37(7.75,-0.75) 38(7.75,-0.25) 39(7.75,0.25) 40(7.75,0.75) 41(7.75,1.25) 42(7.75,1.75) 43(7.75,2.25) 44(7.75,2.75) 45(7.75,3.25) 46(7.75,3.75) 47(7.75,4.25) 48(7.75,4.75) 77(-7.75,4.75) 78(-7.75,4.25) 79(-7.75,3.75) 80(-7.75,3.25) 81(-7.75,2.75) 82(-7.75,2.25) 83(-7.75,1.75) 84(-7.75,1.25) 85(-7.75,0.75) 86(-7.75,0.25) 87(-7.75,-0.25) 88(-7.75,-0.75) 89(-7.75,-1.25) 90(-7.75,-1.75) 91(-7.75,-2.25) 92(-7.75,-2.75) 93(-7.75,-3.25) 94(-7.75,-3.75) 95(-7.75,-4.25) 96(-7.75,-4.75)
  rect 2.997x2.997 smd: 97(-4.95,-1.65) 98(-1.65,-1.65) 99(1.65,-1.65) 100(4.95,-1.65) 101(4.95,1.65) 102(1.65,1.65) 103(-1.65,1.65) 104(-4.95,1.65)
  rect 0.711x0.711 smd: 105(-7.505,-5.505) 106(7.505,-5.505) 107(7.505,5.505) 108(-7.505,5.505)
MSOP8-4_9-65
  rect 0.406x1.448 smd: 1(-0.975,-2.325) 2(-0.325,-2.325) 3(0.325,-2.325) 4(0.975,-2.325) 5(0.975,2.325) 6(0.325,2.325) 7(-0.325,2.325) 8(-0.975,2.325)
POWER-3X3-65-5P-ADNR21357
  rect 0.508x0.356 smd: 1(1.4,-0.975) 2(1.4,-0.325) 3(1.4,0.325) 4(1.4,0.975)
  custom 0.57x0.57 smd: 5(0,0)
POWER-5_2X5_55-1_27-7P-1H
  rect 0.508x0.559 smd: 1(-1.905,-2.8) 5(1.905,2.8) 6(0.635,2.8) 7(-0.635,2.8) 8(-1.905,2.8)
  custom 0.463x0.463 smd: 2(0,-2.1)
  rect 4.648x2.54 smd: 9(0,0.55)
QFN8-1_2X1-4
  rect 0.178x0.381 smd: 1(-0.4,-0.46) 3(0.4,-0.46) 5(0.4,0.46) 6(0,0.46) 7(-0.4,0.46)
  rect 0.178x0.508 smd: 2(0,-0.398)
  rect 0.381x0.178 smd: 4(0.56,0) 8(-0.56,0)
QFN12-2X2-4
  rect 0.203x1.092 smd: 1(-0.2,-1.05) 2(0.2,-1.05) 7(0.2,1.05) 8(-0.2,1.05)
  rect 1.092x0.203 smd: 3(1.05,-0.6) 4(1.05,-0.2) 5(1.05,0.2) 6(1.05,0.6) 9(-1.05,0.6) 10(-1.05,0.2) 11(-1.05,-0.2) 12(-1.05,-0.6)
QFN12-3X3-45-0_6H
  rect 0.229x0.787 smd: 1(-0.619,-1.5) 6(-0.619,1.5)
  rect 0.229x1.346 smd: 2(0.101,-1.225) 3(1.001,-1.225)
  rect 0.229x2.286 smd: 4(0.551,0.76)
  rect 0.229x2.261 smd: 5(-0.169,0.76)
  rect 0.787x0.229 smd: 7(-1.5,1.125) 8(-1.5,0.675) 9(-1.5,0.225) 10(-1.5,-0.225) 11(-1.5,-0.675) 12(-1.5,-1.125)
QFN16-2_6X1_8-4-0_55H
  rect 0.203x0.762 smd: 1(-0.6,-0.725)
  rect 0.203x0.66 smd: 2(-0.2,-0.775) 3(0.2,-0.775) 4(0.6,-0.775) 9(0.6,0.775) 10(0.2,0.775) 11(-0.2,0.775) 12(-0.6,0.775)
  rect 0.584x0.203 smd: 5(1.175,-0.6) 8(1.175,0.6) 13(-1.175,0.6) 15(-1.175,-0.2) 16(-1.175,-0.6)
  rect 0.66x0.203 smd: 6(1.175,-0.2) 7(1.175,0.2) 14(-1.175,0.2)
QFN16-4X4-65-17P-MAX4063
  rect 0.381x1.143 smd: 1(-0.975,-2.025) 2(-0.325,-2.025) 3(0.325,-2.025) 4(0.975,-2.025) 9(0.975,2.025) 10(0.325,2.025) 11(-0.325,2.025) 12(-0.975,2.025)
  rect 1.143x0.381 smd: 5(2.025,-0.975) 6(2.025,-0.325) 7(2.025,0.325) 8(2.025,0.975) 13(-2.025,0.975) 14(-2.025,0.325) 15(-2.025,-0.325) 16(-2.025,-0.975)
  rect 2.108x2.108 smd: 17(0,0)
QFN24-5_5X3_5-5-25P-SN74AVC8T245
  custom 0.07x0.07 smd: 1(-2.725,-0.75) 2(-2.25,-1.725) 3(-1.75,-1.725) 4(-1.25,-1.725) 5(-0.75,-1.725) 6(-0.25,-1.725) 7(0.25,-1.725) 8(0.75,-1.725) 9(1.25,-1.725) 10(1.75,-1.725) 11(2.25,-1.725) 12(2.725,-0.75) 13(2.725,0.75) 14(2.25,1.725) 15(1.75,1.725) 16(1.25,1.725) 17(0.75,1.725) 18(0.25,1.725) 19(-0.25,1.725) 20(-0.75,1.725) 21(-1.25,1.725) 22(-1.75,1.725) 23(-2.25,1.725) 24(-2.725,0.75)
  custom 0.512x0.512 smd: 25(0,0)
QFN28-5X5-5-29P-GL3213-OHY01
  rect 0.305x0.991 smd: 1(-1.5,-2.6) 2(-1,-2.6) 3(-0.5,-2.6) 4(0,-2.6) 5(0.5,-2.6) 6(1,-2.6) 7(1.5,-2.6) 15(1.5,2.6) 16(1,2.6) 17(0.5,2.6) 18(0,2.6) 19(-0.5,2.6) 20(-1,2.6) 21(-1.5,2.6)
  rect 0.991x0.305 smd: 8(2.6,-1.5) 9(2.6,-1) 10(2.6,-0.5) 11(2.6,0) 12(2.6,0.5) 13(2.6,1) 14(2.6,1.5) 22(-2.6,1.5) 23(-2.6,1) 24(-2.6,0.5) 25(-2.6,0) 26(-2.6,-0.5) 27(-2.6,-1) 28(-2.6,-1.5)
  custom 0.887x0.887 smd: 29(0,0)
QFN32-4X4-4-33P-0_9H
  custom 0.051x0.051 smd: 1(-1.4,-2.1) 8(1.4,-2.1) 9(2.1,-1.4) 16(2.1,1.4) 17(1.4,2.1) 24(-1.4,2.1) 25(-2.1,1.4) 32(-2.1,-1.4)
  rect 0.203x0.991 smd: 2(-1,-2.1) 3(-0.6,-2.1) 4(-0.2,-2.1) 5(0.2,-2.1) 6(0.6,-2.1) 7(1,-2.1) 18(1,2.1) 19(0.6,2.1) 20(0.2,2.1) 21(-0.2,2.1) 22(-0.6,2.1) 23(-1,2.1)
  rect 0.991x0.203 smd: 10(2.1,-1) 11(2.1,-0.6) 12(2.1,-0.2) 13(2.1,0.2) 14(2.1,0.6) 15(2.1,1) 26(-2.1,1) 27(-2.1,0.6) 28(-2.1,0.2) 29(-2.1,-0.2) 30(-2.1,-0.6) 31(-2.1,-1)
  rect 2.692x2.692 smd: 33(0,0)
QFN32-4X4-4-33P-ISL95812HRZ-SMT
  custom 0.05x0.05 smd: 1(-1.4,-2) 8(1.4,-2) 9(2,-1.4) 16(2,1.4) 17(1.4,2) 24(-1.4,2) 25(-2,1.4) 32(-2,-1.4)
  rect 0.203x0.787 smd: 2(-1,-2) 3(-0.6,-2) 4(-0.2,-2) 5(0.2,-2) 6(0.6,-2) 7(1,-2) 18(1,2) 19(0.6,2) 20(0.2,2) 21(-0.2,2) 22(-0.6,2) 23(-1,2)
  rect 0.787x0.203 smd: 10(2,-1) 11(2,-0.6) 12(2,-0.2) 13(2,0.2) 14(2,0.6) 15(2,1) 26(-2,1) 27(-2,0.6) 28(-2,0.2) 29(-2,-0.2) 30(-2,-0.6) 31(-2,-1)
  rect 2.642x2.642 smd: 33(0,0)
QFN48-6X6-4-49P-IT8801
  rect 0.203x1.016 smd: 1(-2.2,-3.088) 2(-1.8,-3.088) 3(-1.4,-3.088) 4(-1,-3.088) 5(-0.6,-3.088) 6(-0.2,-3.088) 7(0.2,-3.088) 8(0.6,-3.088) 9(1,-3.088) 10(1.4,-3.088) 11(1.8,-3.088) 12(2.2,-3.088) 25(2.2,3.088) 26(1.8,3.088) 27(1.4,3.088) 28(1,3.088) 29(0.6,3.088) 30(0.2,3.088) 31(-0.2,3.088) 32(-0.6,3.088) 33(-1,3.088) 34(-1.4,3.088) 35(-1.8,3.088) 36(-2.2,3.088)
  rect 1.016x0.203 smd: 13(3.088,-2.2) 14(3.088,-1.8) 15(3.088,-1.4) 16(3.088,-1) 17(3.088,-0.6) 18(3.088,-0.2) 19(3.088,0.2) 20(3.088,0.6) 21(3.088,1) 22(3.088,1.4) 23(3.088,1.8) 24(3.088,2.2) 37(-3.088,2.2) 38(-3.088,1.8) 39(-3.088,1.4) 40(-3.088,1) 41(-3.088,0.6) 42(-3.088,0.2) 43(-3.088,-0.2) 44(-3.088,-0.6) 45(-3.088,-1) 46(-3.088,-1.4) 47(-3.088,-1.8) 48(-3.088,-2.2)
  rect 4.318x4.318 smd: 49(0,0)
QFN88-10X10-4-89P-FL5001
  rect 0.203x0.991 smd: 1(-4.2,-5.1) 2(-3.8,-5.1) 3(-3.4,-5.1) 4(-3,-5.1) 5(-2.6,-5.1) 6(-2.2,-5.1) 7(-1.8,-5.1) 8(-1.4,-5.1) 9(-1,-5.1) 10(-0.6,-5.1) 11(-0.2,-5.1) 12(0.2,-5.1) 13(0.6,-5.1) 14(1,-5.1) 15(1.4,-5.1) 16(1.8,-5.1) 17(2.2,-5.1) 18(2.6,-5.1) 19(3,-5.1) 20(3.4,-5.1) 21(3.8,-5.1) 22(4.2,-5.1) 45(4.2,5.1) 46(3.8,5.1) 47(3.4,5.1) 48(3,5.1) 49(2.6,5.1) 50(2.2,5.1) 51(1.8,5.1) 52(1.4,5.1) 53(1,5.1) 54(0.6,5.1) 55(0.2,5.1) 56(-0.2,5.1) 57(-0.6,5.1) 58(-1,5.1) 59(-1.4,5.1) 60(-1.8,5.1) 61(-2.2,5.1) 62(-2.6,5.1) 63(-3,5.1) 64(-3.4,5.1) 65(-3.8,5.1) 66(-4.2,5.1)
  rect 0.991x0.203 smd: 23(5.1,-4.2) 24(5.1,-3.8) 25(5.1,-3.4) 26(5.1,-3) 27(5.1,-2.6) 28(5.1,-2.2) 29(5.1,-1.8) 30(5.1,-1.4) 31(5.1,-1) 32(5.1,-0.6) 33(5.1,-0.2) 34(5.1,0.2) 35(5.1,0.6) 36(5.1,1) 37(5.1,1.4) 38(5.1,1.8) 39(5.1,2.2) 40(5.1,2.6) 41(5.1,3) 42(5.1,3.4) 43(5.1,3.8) 44(5.1,4.2) 67(-5.1,4.2) 68(-5.1,3.8) 69(-5.1,3.4) 70(-5.1,3) 71(-5.1,2.6) 72(-5.1,2.2) 73(-5.1,1.8) 74(-5.1,1.4) 75(-5.1,1) 76(-5.1,0.6) 77(-5.1,0.2) 78(-5.1,-0.2) 79(-5.1,-0.6) 80(-5.1,-1) 81(-5.1,-1.4) 82(-5.1,-1.8) 83(-5.1,-2.2) 84(-5.1,-2.6) 85(-5.1,-3) 86(-5.1,-3.4) 87(-5.1,-3.8) 88(-5.1,-4.2)
  rect 8.103x8.103 smd: 89(0,0)
R0201
  rect 0.203x0.381 smd: 1(-0.225,0) 2(0.225,0)
R0402
  custom 0.12x0.12 smd: 1(0.39,0) 2(-0.39,0)
R0603
  rect 0.686x0.813 smd: 1(0.6,0) 2(-0.6,0)
R1206
  rect 1.219x1.626 smd: 1(1.4,0) 2(-1.4,0)
S0201
  rect 0.343x0.381 smd: 1(-0.225,0) 2(0.225,0)
S0402
  custom 0.125x0.125 smd: 1(0.39,0) 2(-0.39,0)
S0603
  rect 1.041x0.813 smd: 1(0.6,0) 2(-0.6,0)
S0805
  rect 1.346x1.372 smd: 1(0.88,0) 2(-0.88,0)
SENSOR-1_3X0_9-5-4P
  rect 0.457x0.254 smd: 1(-0.625,0.25) 2(-0.625,-0.25) 3(0.625,-0.25) 4(0.625,0.25)
SENSOR-2_4X2-65-6P
  rect 0.762x0.305 smd: 1(0.625,-0.65)
  custom 0.075x0.075 smd: 2(0.625,0) 3(0.625,0.65) 4(-0.625,0.65) 5(-0.625,0) 6(-0.625,-0.65)
SHORT8X4
  rect 0.108x0.102 smd: 1(-0.047,0) 2(0.047,0)
SOT23-1_38-5-3P
  rect 0.533x0.381 smd: 1(0.69,0.5) 2(0.69,-0.5) 3(-0.69,0)
SOT23-2-95-3P
  rect 0.711x0.559 smd: 1(1,0.95) 2(1,-0.95) 3(-1,0)
SOT23-2_8-65-8P-RT6218
  rect 0.457x0.991 smd: 1(-0.975,-1.3) 2(-0.325,-1.3) 3(0.325,-1.3) 4(0.975,-1.3) 5(0.975,1.3) 6(0.325,1.3) 7(-0.325,1.3) 8(-0.975,1.3)
SOT23-2_38-95-3P
  rect 0.787x0.533 smd: 1(1.19,0.95) 2(1.19,-0.95) 3(-1.19,0)
SOT23-5-2_8-95-5P-G708
  rect 1.194x0.533 smd: 1(1.5,-0.95) 2(1.5,0) 3(1.5,0.95) 4(-1.5,0.95) 5(-1.5,-0.95)
SOT23-5-2_794-9395-5P
  rect 1.346x0.584 smd: 1(1.32,-0.94) 2(1.32,0) 3(1.32,0.94) 4(-1.32,0.94) 5(-1.32,-0.94)
SOT23-8-2_8-65-8P
  rect 0.381x1.346 smd: 1(-0.975,-1.325) 2(-0.325,-1.325) 3(0.325,-1.325) 4(0.975,-1.325) 5(0.975,1.325) 6(0.325,1.325) 7(-0.325,1.325) 8(-0.975,1.325)
SPAD-RE197X787NP
  rect 5.004x19.99 smd: 1(0,0)
SPAD-RE295X472NP
  rect 7.493x11.989 smd: 1(0,0)
SPAD-RE394X118NP
  rect 10.008x2.997 smd: 1(0,0)
SW-NTC316-AD1T-A160T-4P
  rect 1.194x0.991 smd: 1(2.8,0.85) 3(-2.8,0.85)
  rect 1.194x0.991 hole 0.711: 2(2.65,-0.85) 4(-2.65,-0.85)
TP2050
  round 0.508 smd: 1(0,0)
UB31-AUSB0295-P007A-24P
  round 0.813 hole 0.813 unplated: (-3.6,0)
  oval 0.813x0.762 hole 0.813x0.762 unplated: (3.6,0)
  oval 1.092x1.956 hole 0.61x1.448: 1(-4.8,-0.875) 2(4.8,-0.875)
  oval 1.092x2.388 hole 0.61x1.6: 3(-5.8,-5.1) 4(5.8,-5.1)
  rect 0.254x1.092 smd: A1(-2.75,0.66) A2(-2.25,0.66) A3(-1.75,0.66) A4(-1.25,0.66) A5(-0.75,0.66) A6(-0.25,0.66) A7(0.25,0.66) A8(0.75,0.66) A9(1.25,0.66) A10(1.75,0.66) A11(2.25,0.66) A12(2.75,0.66)
  round 0.61 hole 0.457: B1(2.8,-0.55) B2(2.4,-1.35) B3(1.6,-1.35) B4(1.35,-0.55) B5(0.8,-1.35) B6(0.4,-0.55) B7(-0.4,-0.55) B8(-0.8,-1.35) B9(-1.35,-0.55) B10(-1.6,-1.35) B11(-2.4,-1.35) B12(-2.8,-0.55)
unnamed
  rect 0.102x0.203 smd: 1(0,0)
WSON8-6X5-1_27-9P-W25Q64FWZPIG
  rect 0.508x1.499 smd: 1(-1.905,-2.85) 2(-0.635,-2.85) 3(0.635,-2.85) 4(1.905,-2.85) 5(1.905,2.85) 6(0.635,2.85) 7(-0.635,2.85) 8(-1.905,2.85)
  rect 4.293x3.404 smd: 9(0,0)
WTB-50458-00801-V02-8P-L
  rect 0.559x1.295 smd: 1(-7,5.025) 2(-5,5.025) 3(-3,5.025) 4(-1,5.025) 5(1,5.025) 6(3,5.025) 7(5,5.025) 8(7,5.025)
  rect 1.295x2.057 smd: 9(-10.1,0) 10(10.1,0)
XTL-2_5X2-1_7X1_3-1H
  rect 1.194x0.991 smd: 1(-0.85,-0.65) 2(0.85,-0.65) 3(0.85,0.65) 4(-0.85,0.65)
XTL-2_5X2-1_85X1_55
  rect 0.991x0.889 smd: 1(-0.925,-0.775) 2(0.925,-0.775) 3(0.925,0.775) 4(-0.925,0.775)
XTL-3_2X2_5-2_2X1_7-0_8H
  rect 1.397x1.194 smd: 1(-1.1,-0.85) 2(1.1,-0.85) 3(1.1,0.85) 4(-1.1,0.85)

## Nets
3V3_PCSCL: Q3.1(S) R12.1 R90154.1
3V3_PCSDA: Q4.1(S) R13.1 R90155.1
AVDD18_SOC: C1002.1 C1003.1 C1004.1 C1011.2 C4203.1 C5002.2 C7102.1 C7210.1 R91091.1 SH2101.1 U1001.AB13 U1001.AC7 U1001.AH19 U1001.AH21 U1001.B2 U1001.D23 U1001.F27 U1001.H23
AVSS28_AUD: C6101.2 C6102.1 C6103.1 SH6101.2 SH6204.2 U2001.J5
DVDD18_DIG: C2141.1 U2001.J8
DVDD_CORE: C1830.1 C1831.1 C1832.1 C1833.1 C1834.1 C1835.1 C2010.2 C2011.2 C6701.1 C10472.2 C10473.2 C10480.2 C10481.2 PL2003.2 R90877.1 SH1806.1 U1001.AB7 U1001.AB22 U1001.AC22 U1001.AD7 U1001.H21 U1001.J11 U1001.J16 U1001.K12 U1001.K16 U1001.L11 U1001.L15 U1001.M12 U1001.M16 U1001.N11 U1001.N15 U1001.P7 U1001.P12 U1001.P16 U1001.P21 U1001.R7 U1001.R8 U1001.R11 U1001.R15 U1001.T7 U1001.T8 U1001.T12 U1001.T16 U1001.U15 U1001.U19 U1001.U21 U1001.V16 U1001.V20 U1001.V27 U1001.W15 U1001.W19 U1001.Y16 U1001.Y20
DVDD_CORE_PMIC_FB: SH1806.2 U2001.C16
DVDD_CORE_PMIC_GND: SH1805.1 U2001.B16
DVDD_GPU: C1808.2 C1810.2 C1811.1 C1812.2 C1826.2 C1828.2 C2026.1 C2027.1 C10478.1 C10479.1 PL2008.2 SH1802.2 U1001.J19 U1001.J20 U1001.L19 U1001.M20 U1001.N19 U1001.P20 U1001.R19 U1001.T20
DVDD_GPU_PMIC_FB: SH1802.1 U2001.D14
DVDD_GPU_PMIC_GND: SH1801.2 U2001.C15
DVDD_PROC_B: C1813.2 C1814.2 C1815.2 C1816.2 C1822.2 C1829.2 C1840.2 C1841.2 C1842.2 C2003.2 C2005.1 C2021.1 PL2001.2 SH1803.2 U1001.AA10 U1001.AB9 U1001.AC9 U1001.AC10 U1001.AC11 U1001.AD9 U1001.AD10
DVDD_PROC_B_PMIC_FB: SH1803.1 U2001.D6
DVDD_PROC_B_PMIC_GND: SH1804.2 U2001.D7
DVDD_PROC_L: C1817.2 C1819.2 C1821.2 C1823.2 C1827.2 C1843.2 C2002.1 C2008.1 C10468.1 C10474.1 C10475.1 PL2002.2 SH1807.2 U1001.U7 U1001.U8 U1001.U9 U1001.U10 U1001.W9 U1001.W11
DVDD_PROC_L_PMIC_FB: SH1807.1 U2001.E9
DVDD_PROC_L_PMIC_GND: SH1808.2 U2001.D10
DVDD_SRAM_CORE: C1836.2 C1837.2 C2146.1 U1001.AC14 U1001.J12 U1001.T11 U1001.V21 U1001.Y15 U2001.P14
DVDD_SRAM_PROC_B: C1824.1 C1825.1 C2147.1 U1001.AC13 U2001.P12
DVDD_SRAM_PROC_L: C1838.1 C1839.1 C2144.1 U1001.W7 U2001.R13
DVDD_VSRAM_GPU_PMU: C1818.1 C1820.1 C2145.1 U1001.T18 U2001.R14
DVSS18_IO: C2139.2 C2140.2 SH2144.1 U2001.L8
GND_SMPS: C2001.2 SH2001.1 U2001.E1
GND_VCORE: C2009.2 U2001.A13 U2001.B13
GND_VDRAM1: C2028.2 U2001.H15
GND_VGPU: C2025.2 U2001.D12 U2001.D13
GND_VMODEM: C2013.2 U2001.G15 U2001.G16
GND_VPA: C2016.2 U2001.B4
GND_VPROC11: C2004.2 U2001.A8 U2001.B8
GND_VPROC12: C2007.2 U2001.D8 U2001.D9
GND_VREF: C2138.2 SH2140.1 U2001.N13
GND_VS1: C2023.2 U2001.A3 U2001.B3
GND_VS2: C2024.2 U2001.L14
VBAT_IN_N: NC288.1 R90494.1
VBAT_IN_P: NC287.1 R90495.1
227E_DET_TRIGGER_L: R90763.1 U6541.B1
227E_RING2: R90759.1 U6541.D1
227E_RING2_SENSE: R90761.1 U6541.C4
227E_SLEEVE: R90760.1 U6541.D3
227E_SLEEVE_SENSE: R90762.1 U6541.D4
227E_TIP: R90764.1 U6541.C1
ACCDET: R6225.1 U2001.K6
ACCEL_INT_AP_ODL: R90569.1 U1001.T22
ACOK_OD: R709.1 R91175.2 R91186.1 U124.A6
ALS_RGB_INT_ODL: R91209.1 U6574.5
AMP_L_EN: R90267.2 U6503.A1
AMP_L_GAIN: R90706.1 R90707.2 U6503.B2
AMP_L_POWER: C9022.1 C9023.2 R90706.2 R90708.2 U6503.A2(VDD)
AMP_R_EN: R90268.2 U6502.A1
AMP_R_GAIN: R90265.1 R90266.2 U6502.B2
AMP_R_POWER: C9020.1 C9021.2 R90265.2 R90530.2 U6502.A2(VDD)
ANX7625_HPD: Q791.3 R91233.1 U6578.E7
ANX7625_SCL: Q800.4 R91241.2 R91255.2 U6578.D7
ANX7625_SDA: Q799.4 R91240.2 R91256.2 U6578.C7
ANX7625_XTAL_IN: C10672.1 R91239.2 R91259.2 Y3.3
ANX7625_XTAL_IN_R: R91258.2 R91259.1 U6578.D1
ANX7625_XTAL_OUT: C10671.1 R91239.1 R91257.2 U6578.C1(XTAL_OUT) Y3.1
AP_CLK26M_S0: C8001.1 R8001.2 U1001.AE17
AP_CTS_BT_RTS: TP9067.1 U1001.AG25 U1007.57
AP_EC_WATCHDOG_L: R90453.1 R90906.2 U1001.M23 U6517.B5
AP_FLASH_WP_ODL: R90611.2 U1001.R25
AP_H1_I2C_SCL: R90434.1 R90973.1 U124.H8
AP_H1_I2C_SDA: R90410.1 R90974.1 U124.D8
AP_IN_SLEEP_L: R90525.2 U6517.C5
AP_MSDC1_CLK: R90340.1 R90696.1 U1001.AC24
AP_MSDC1_CMD: R90341.1 R90697.1 U1001.AD26
AP_MSDC1_DAT0: R90342.1 R90699.1 U1001.AD24
AP_MSDC1_DAT1: R90343.1 R90698.1 U1001.AE26
AP_MSDC1_DAT2: R90591.1 R90701.1 U1001.AC23
AP_MSDC1_DAT3: R90700.1 U1001.AD27
AP_RTS_BT_CTS: TP9065.1 U1001.AG24 U1007.54
AP_RXD1_BT_TXD: TP9066.1 U1001.H3 U1007.55
AP_SKU_ID: C10438.1 R90725.1 R90726.1 U1001.AG18
AP_SPI_FLASH_CLK: R90431.2 U1001.AA22
AP_SPI_FLASH_CS_L: R90428.1 U1001.AB25
AP_SPI_FLASH_MISO: R90429.1 U1001.W22
AP_SPI_FLASH_MOSI: R90430.2 U1001.Y22
AP_SPI_H1_CLK: R90415.1 R90976.2 R91082.2 U124.F9
AP_SPI_H1_CS_L: R90409.1 R90975.2 R91081.2 U124.J8
AP_SPI_H1_MISO: R91079.2 U124.H9
AP_SPI_H1_MOSI: R91080.2 U124.C9
AP_TXD1_BT_RXD: TP9064.1 U1001.H4 U1007.56
AP_UART_VREF: C415.1 CON16.18 R330.1
AP_WARM_RST_REQ: R90688.2 U1001.K22
AU_HPL: R6206.1 R90773.1 U2001.H4
AU_HPR: R6207.1 R90774.1 U2001.G4
AU_MICBIAS0: C6102.2 C10635.1 J15.1 U2001.K5
AU_MICBIAS1: C6103.2 R6209.2 R90738.1 U2001.L5
AU_REFN: C10447.1 R90782.1 U2001.H5
AU_VIN1_N: C6229.1 U2001.L3
AU_VIN1_P: C6230.1 U2001.L4
AUD_CLK_MISO: R2205.1 U1001.M25 U2001.H10
AUD_CLK_MOSI: U1001.M24 U2001.L11
AUD_DAT_MISO0: R1007.1 R1010.2 U1001.N24 U2001.J11
AUD_DAT_MISO1: R1011.2 U1001.L23 U2001.H11
AUD_DAT_MOSI0: R1009.1 R1012.2 U1001.J22 U2001.J9
AUD_DAT_MOSI1: U1001.N27 U2001.L10
AUD_SYNC_MISO: R2206.1 U1001.M26 U2001.J10
AUD_SYNC_MOSI: U1001.L26 U2001.K10
AUX_IN0_NTC: C1502.1 NTC1501.1 R1501.2 U1001.AF19
AUX_IN1_NTC: C1503.1 NTC1502.1 R1502.2 U1001.AF18
AUXIN2: C10440.1 R90729.1 R90732.1 U1001.AE19
BASE_ACCEL_INT_ODL: R90568.1 U6517.H3
BATADC: C2302.1 SH2302.2 U2001.L13
BATON: R2301.2 R90597.2 U2001.L12
BATT_DISABLE_ODL: C299.1 Q55.2 Q785.1(S) R420.2 U124.C8
BATT_SCL_1V8: Q793.1(S) R91248.2 U6517.F4
BATT_SCL_3V3: CON15.4 Q793.3 R91246.2 R91296.2
BATT_SDA_1V8: Q794.1(S) R91249.2 U6517.H5
BATT_SDA_3V3: CON15.3 Q794.3 R91247.2 R91297.2
BATT_TEMP: CON15.5 R293.1 R91183.1 R91184.1
BB_BATGONE: R538.1 R91184.2
BC12_C0_ADDR: R91062.1 U6555.10
BC12_C0_EN_L: R91061.1 U6555.11
BC12_EC_INT_ODL: R619.2 R91179.1 U6555.5
BMM150_CSB: R91146.2 U6575.A5
BMM150_SDO: R91144.2 U6575.C1
BOOTBLOCK_EC_CLK: U6517.G8 U6522.9
BOOTBLOCK_EC_CMD: U6517.F7 U6522.16
BOOTBLOCK_EC_DAT0: U6517.F8 U6522.3
BOOTBLOCK_EN_L: R90554.2 R90692.2 R91031.1 TP9079.1 U1001.AA5
BT_EN_1V8: Q724.1(S) R90900.2 U1001.K6
BT_EN_3V3: C10647.1 Q724.3 R90627.2 R90901.2 U1007.63
BT_HOST_WAKE: R90844.1 U1001.AF26
BTN_GND: CON7102.27 CON9105.27 R90859.2 R91143.1
BUCKBOOST_ACIN: C533.2 R503.2 R504.1 U6.19
BUCKBOOST_ASGATE: Q789.4 Q795.2 Q801.4 TP109.1 U6.13
BUCKBOOST_CMIN: R521.1 R91192.2 U6.20
BUCKBOOST_CMOUT: TP110.1 U6.26
BUCKBOOST_COMP: C10452.1 R90740.2 U6.28
BUCKBOOST_CSN: C447.2 C10492.1 R90837.2 U6.14
BUCKBOOST_CSP: C447.1 C10491.1 R90836.2 U6.15
CHARGER_IADP: C495.1 R91195.1
CHARGER_PMON: C594.1 R174.2 U6.30
CHRLDO: C2303.1 R2304.2 U2001.K13
CKDN: R189.2 U6578.H8
CKDP: R190.2 U6578.G8
CLK_32K_WLAN: R90845.2 U2001.G12
COMPASS_I2C_SCL: R90857.2 U6575.A3
COMPASS_I2C_SCL_R: R90857.1 R90872.1 U6404.3
COMPASS_I2C_SDA: R90856.2 U6575.B4
COMPASS_I2C_SDA_R: R90856.1 R90871.1 U6404.2
COMPASS_INT_L: TP9084.1 U6575.D2
COMPASS_RDY_TP: TP9083.1 U6575.D4
CON_EDP_BKLTEN_3V3: J15.23 Q705.3 R90952.2
CTP_I2C_SCL: J15.37 Q777.1(S) R90612.2 R91127.2
CTP_I2C_SDA: J15.36 Q776.1(S) R90614.2 R91126.2
